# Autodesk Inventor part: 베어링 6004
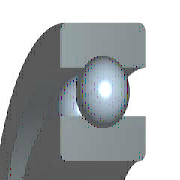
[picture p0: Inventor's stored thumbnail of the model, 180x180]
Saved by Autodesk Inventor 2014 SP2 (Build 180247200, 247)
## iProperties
IsCustomPart: 1
Created: 2012-02
Part Number: 베어링 6004
Material: 강철, 연강
Description: 깊은 그루브 볼 베어링
Document SubType Name: Modeling
Standard: KS B 2023
Designer: mduedu
Standards Organization: KS
Language: ko-KR
Size Designation: 6004 - 20 x 42 x 12
Categories: <MemberInstance><Categories><Category DisplayName="샤프트 부품" InternalName="7f7aeb1f-a693-4053-b835-cee3144e0d98" Mnemonic="SHFT"><Category DisplayName="베어링" Inter
Density: 1 g/cm^3
Appearance: 노란색
Author: mduedu
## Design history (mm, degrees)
sketch "스케치" dims "d0" = 5.72 (= -0.26 x WD + 0.26 x BD)
  geometry: L1 (3.14, 15.5)-(8.86, 15.5); L2 (6, 15.5)-(6, 12.64); L3 (6, 15.5)-(6, 18.36); L4 (3.875, 13.586)-(0, 13.586); L5 (0, 10)-(12, 10); L6 (3.875, 17.414)-(0, 17.414); L7 (0, 21)-(12, 21); L8 (12, 10)-(12, 13.586); L9 (8.125, 13.586)-(12, 13.586); L10 (8.125, 17.414)-(12, 17.414); L11 (12, 21)-(12, 17.414); L12 (-1.4, 0)-(8.4, 0) reference; L13 (0, -0.3)-(0, 5.3) reference
  constraints: 22 end point, 4 point on line, 2 collinear, 2 perpendicular, 2 symmetric about line, 1 midpoint, 1 parallel, 14 other
  dimensions: "d9" = 20 diameter of L5 L12 (= WD); "d11" = 42 diameter of L7 L12 (= BD); "d12" = 12 distance between parallel lines of L8 L13 (= KB); "d13" = 27.172 diameter of L9 L12 (= 0.326 x BD + 0.674 x WD)
revolve "본체" stored, may be unused: angle "d6" = 90 deg
revolve "볼" stored, may be unused: angle "d7" = 90 deg
pattern_circular "IDS_ARRAYBALL[SIMPL:T]" dims angle "d3" = 360 deg
body "Solid1"
fillet "모깎기1" dims "d1" = 0.6 (= KRS)
other parameters: "WD" = 20 [user parameter; used in 5 equation terms], "BD" = 42 [user parameter; used in 5 equation terms], "KB" = 12 [user parameter; used in 1 equation term], "KRS" = 0.6 [user parameter; used in 1 equation term], "d4" = 0, "d5" = 0, "d8" = 0, "d14" = 0, "d15" = 0, "BBA" = 0 [user parameter], "BC0" = 5000000 [user parameter], "BC" = 9360000 [user parameter], "BR" = 21 (= 0.5 x BD) [user parameter]
